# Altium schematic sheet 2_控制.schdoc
size 309 x 223 mm; Symbol: Sheet-Symbol_A4; Device: Sheet-Symbol_A4; Company: 嘉立创EDA; Version: V1.0; Page Size: A4; @Project Name: 辉光管时钟成品; @Page Count: 2; @Update Date: 2024-01-22; @Create Date: 2024-01-22; @Schematic Name: 驱动+控制部分; @Page No: 2; @Page Name: 控制.驱动+控制部分
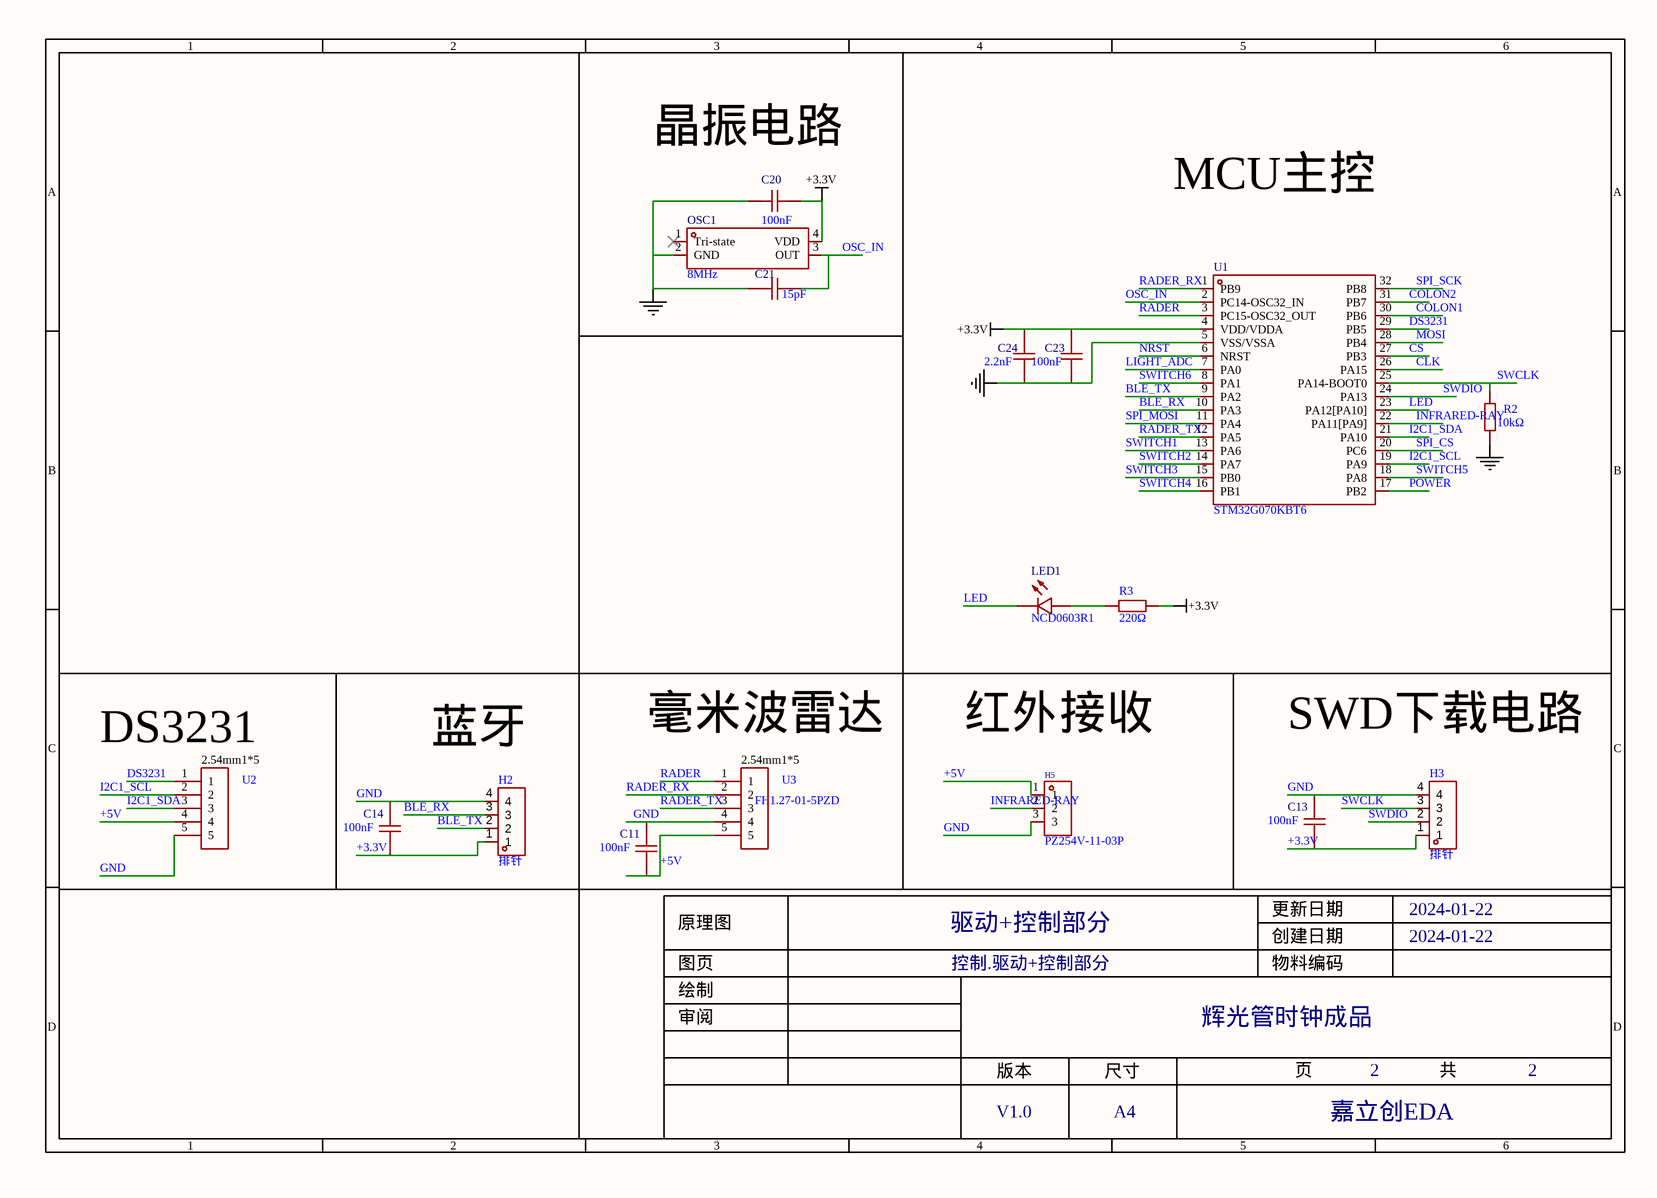
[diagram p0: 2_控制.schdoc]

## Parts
C11  100nF  [C0603]
C13  100nF  [C0603]
C14  100nF  [C0603]
C20  100nF  [C0603]
C21  15pF  [C0603]
C23  100nF  [C0603]
C24  2.2nF  [C0603]
H2  排针  [SIP-2.54MM-4P-CJT-H8.54]
H3  排针  [SIP-2.54MM-4P-CJT-H8.54]
H5  PZ254V-11-03P  [HDR-TH_3P-P2.54-V-M]
LED1  NCD0603R1  [LED0603-RD_RED]
OSC1  8MHz  [OSC-SMD_4P-L3.2-W2.5-BL-1]
R2  10kΩ  [r0603]
R3  220Ω  [r0603]
U1  STM32G070KBT6  [LQFP-32_L7.0-W7.0-P0.80-LS9.0-BL]
U2  (no value)  [2.54mm1*5]
U3  FH1.27-01-5PZD  [HDR-TH_5P-P1.27-V-M]

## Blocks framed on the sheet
晶振电路: C20 C21 OSC1
MCU主控: C23 C24 LED1 R2 R3 U1
DS3231: U2
蓝牙: C14 H2
毫米波雷达: C11 U3
SWD下载电路: C13 H3
红外接收: H5

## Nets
+3.3V: C13.1 C14.1 C20.1 C23.2 C24.2 H2.1 H3.1 OSC1.4(VDD) R3.1 U1.4(VDD/VDDA)
GND: C11.2 C13.2 C14.2 C20.2 C21.2 C23.1 C24.1 H2.4 H3.4 H5.3 OSC1.2(GND) R2.1 U1.5(VSS/VSSA) U2.5 U3.4
+5V: C11.1 H5.1 U2.4 U3.5
BLE_RX: H2.3 U1.10(PA3)
BLE_TX: H2.2 U1.9(PA2)
CLK: U1.26(PA15)
COLON1: U1.30(PB6)
COLON2: U1.31(PB7)
CS: U1.27(PB3)
DS3231: U1.29(PB5) U2.1
I2C1_SCL: U1.19(PA9) U2.2
I2C1_SDA: U1.21(PA10) U2.3
INFRARED-RAY: H5.2 U1.22(PA11[PA9])
LED: LED1.1(K) U1.23(PA12[PA10])
LIGHT_ADC: U1.7(PA0)
MOSI: U1.28(PB4)
NRST: U1.6(NRST)
OSC_IN: C21.1 OSC1.3(OUT) U1.2(PC14-OSC32_IN)
POWER: U1.17(PB2)
RADER: U1.3(PC15-OSC32_OUT) U3.1
RADER_RX: U1.1(PB9) U3.2
RADER_TX: U1.12(PA5) U3.3
SPI_CS: U1.20(PC6)
SPI_MOSI: U1.11(PA4)
SPI_SCK: U1.32(PB8)
SWCLK: H3.3 R2.2 U1.25(PA14-BOOT0)
SWDIO: H3.2 U1.24(PA13)
SWITCH1: U1.13(PA6)
SWITCH2: U1.14(PA7)
SWITCH3: U1.15(PB0)
SWITCH4: U1.16(PB1)
SWITCH5: U1.18(PA8)
SWITCH6: U1.8(PA1)
NetLED1_2: LED1.2(A) R3.2

Not connected (* = marked no-connect by the designer): OSC1 1(Tri-state)*

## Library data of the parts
C11 C13 C14 C20 C21 C23 C24 = CC0603KRX7R9BB104: Manufacturer: YAGEO(国巨); Add into BOM: yes; Tolerance: ±10%; Voltage Rated: 50V; Temperature Coefficient: X7R
H2 H3 = 排针: Add into BOM: yes
H5 = PZ254V-11-03P: Manufacturer: XFCN(兴飞); Symbol: PZ254V-11-03P_C2937625; Add into BOM: yes; Pitch: 2.54mm; Pin Structure: 1x3P; Circluar Pins/Square Pins: 方针; Current Rating (Max): 3A; Voltage Rating (Max): 250V
LED1 = NCD0603R1_C84263: Manufacturer: 国星光电; Symbol: FC-DA1608HRK-620D; Add into BOM: yes; Emitted Color: 红色; Forward Voltage (VF): 1.6V~2.6V; Forward Current: 20mA; Power Dissipation: 65mW; Lens Color: 无色透明; Dominant Wavelength: 615nm~630nm; Luminous Intensity: 80mcd~220mcd; Viewing Angle: 130°
OSC1 = OT2EL4C4JI-111OLP-8M: Manufacturer: YXC(扬兴晶振); Add into BOM: yes; Supply Voltage: 1.8V~3.3V
R2 R3 = 0805W8F1002T5E_C17414: Manufacturer: UNI-ROYAL(厚声); Symbol: 电阻; Add into BOM: yes; Tolerance: ±1%; Power(Watts): 125mW; Temperature Coefficient: ±100ppm/℃; Overload Voltage (Max): 150V
U1 = STM32G070KBT6: Manufacturer: ST(意法半导体); Add into BOM: yes; CPU Core: ARM Cortex-M0; CPU Maximum Speed: 64MHz; Operating Voltage Range: 2V~3.6V; Program Storage Size: 128KB; Program Memory Type: FLASH; RAM Size: 36KB; GPIO Ports Number: 29; ADC (Bit): 12bit; Peripheral/Function: DMA；PWM; Internal Oscillator: 有
U2 = 2.54mm1*5: Add into BOM: yes
U3 = FH1.27-01-5PZD: Manufacturer: XUNPU(讯普); Symbol: 2.54mm1*5; Add into BOM: yes; Pins Structure: 1x5P; Pitch: 1.27mm; Number of PINs Per Row: 5; Current Rating (Max): 1A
